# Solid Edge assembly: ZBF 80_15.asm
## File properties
Title: Zylinder
Author: bmolnar
Template: iso metric assembly.asm
Last saved by: bmolnar
Revision: 7
Application: Solid Edge
Username: bmolnar
Dokumentum tartalom típus: 1
Document Number: ZBF 80/15
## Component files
Profilrohr.par
Kolbenstange.par
Mutter.par
Kit.par
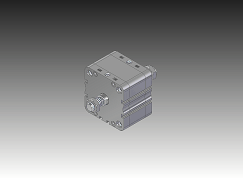
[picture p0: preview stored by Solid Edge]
